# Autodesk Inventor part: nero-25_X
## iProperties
Shininess: 20.0
Length Units: 11269
Angle Units: 11279
Time Units: 11290
Mass Units: 11283
Length Display Precision: 2
Angle Display Precision: 2
Part Number: nero-25_X
Material: Nichtrostender Stahl - 440C
Document SubType Name: Modellieren
Description: Ipc-25 /CXX/M18
Checked By: Alves
Created: 2005-08
Designer: Ohle
Manufacturer: Standard
Standards Organization: Custom
Density: 0.0
Volumn: 0.0
Area: 0.0
PropertySet Name: Model Information
Control State: 0
Master: False
Checked Out: False
BESTELLNUMMER: Ipc-25 /CXX/M18
ME: ST
Title: Ipc Sensoren
Author: Ohle
Comments: keine Bemerkung
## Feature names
1. Grundkörper pico+ [Revolution]
2. Pole [Extrusion]
3. Rundung Pole [Fillet]
4. Verdrehsicherung [Extrusion]
5. Bohrung Ausrichtung [Extrusion]
